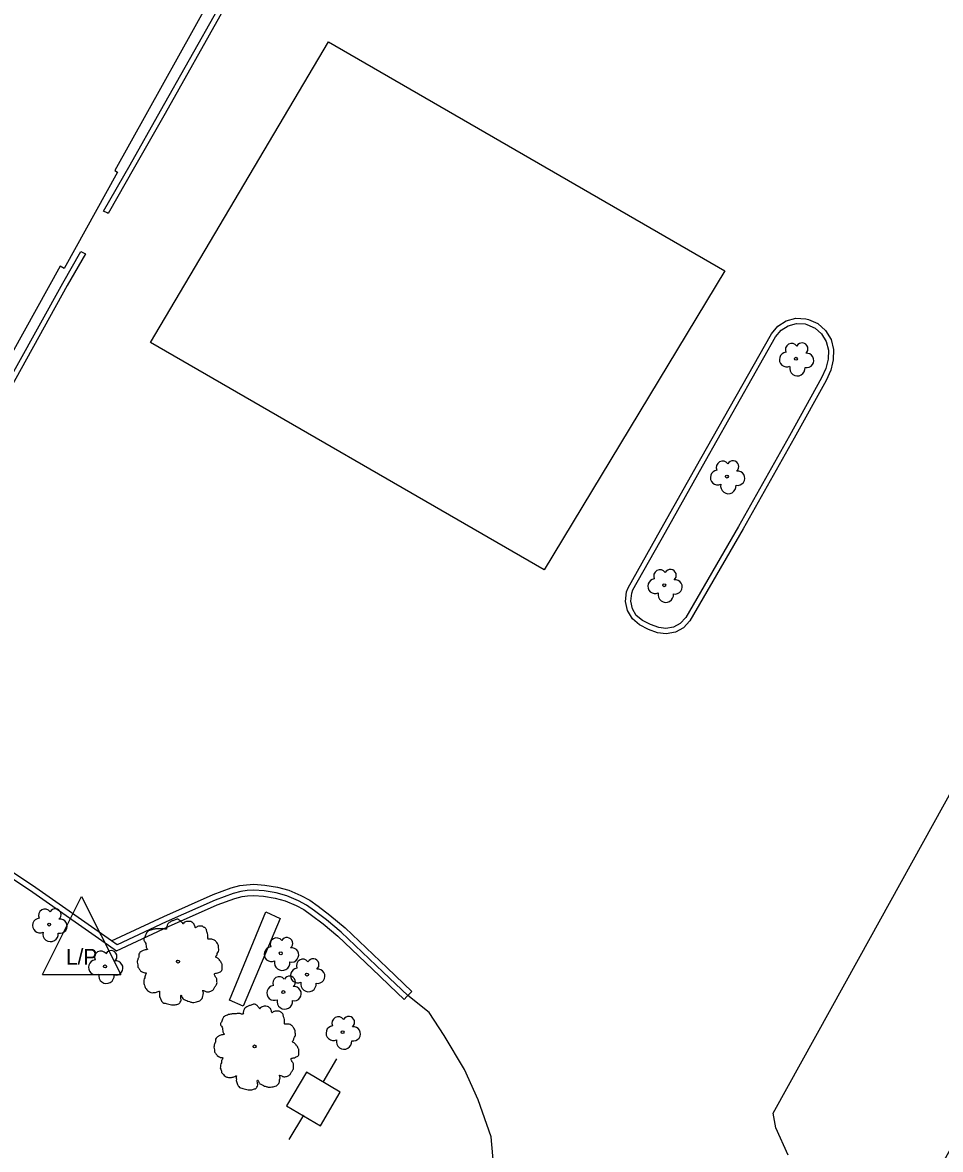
# Model space of a CAD drawing. Extents: x 2161152 to 2175754, y 602179 to 617749.
# Drawn here: x 2173654.5 to 2173771.8, y 616255.2 to 616399.3 of the extents above; entities that cross this region are included whole.
import ezdxf

# ---------------------------------------------------------------- set-up
doc = ezdxf.new("R2010")
doc.units = 0
for name, color, linetype in [('RD_EX_Bldg', 7, 'Continuous'), ('RD_EX_BldgApp', 7, 'Continuous'), ('RD_EX_BldgApp_Sign', 7, 'Continuous'), ('RD_EX_Conc_Curb', 7, 'Continuous'), ('RD_EX_Conc_Gutter', 7, 'Continuous'), ('RD_EX_Parking_Asphalt', 7, 'Continuous'), ('RD_EX_Road', 7, 'Continuous'), ('RD_EX_UT', 7, 'Continuous'), ('RD_EX_VEG', 7, 'Continuous')]:
    doc.layers.add(name, color=color, linetype=linetype)

msp = doc.modelspace()

# ---------------------------------------------------------------- linework, layer by layer
at = {"layer": 'RD_EX_Bldg'}
msp.add_lwpolyline([(2173647.25, 616346.36), (2173617.17, 616363.05), (2173634.68, 616394.61), (2173627.98, 616398.33), (2173643.55, 616426.38), (2173680.5, 616405.88), (2173666.33, 616380.34), (2173666.67, 616380.15), (2173659.83, 616367.83), (2173659.32, 616368.11), (2173647.25, 616346.36)], dxfattribs=at)
at = {"layer": 'RD_EX_BldgApp'}
msp.add_lwpolyline([(2173670.86, 616358.36), (2173693.61, 616396.79), (2173744.23, 616367.52), (2173721.15, 616329.29), (2173670.86, 616358.36)], dxfattribs=at)
at = {"layer": 'RD_EX_BldgApp_Sign'}
msp.add_lwpolyline([(2173680.95, 616274.3), (2173685.62, 616285.58), (2173687.42, 616284.75), (2173682.71, 616273.51), (2173680.95, 616274.3)], dxfattribs=at)
at = {"layer": 'RD_EX_Conc_Curb'}
for points in [[(2173680.13, 616400.76), (2173672.73, 616387.64), (2173668.84, 616380.76), (2173665.48, 616374.84), (2173665.33, 616374.92), (2173664.88, 616375.15), (2173668.26, 616381.09), (2173672.15, 616387.96), (2173679.54, 616401.08)], [(2173650.77, 616349.97), (2173659.66, 616365.96), (2173661.95, 616369.98), (2173662.41, 616369.78), (2173662.56, 616369.7), (2173660.24, 616365.63), (2173651.36, 616349.65)], [(2173739.79, 616322.79), (2173738.98, 616321.9), (2173737.93, 616321.32), (2173736.75, 616321.11), (2173735.64, 616321.26), (2173734.5, 616321.68), (2173733.34, 616322.26), (2173732.43, 616323.05), (2173731.81, 616324.09), (2173731.55, 616325.27), (2173731.69, 616326.48), (2173731.89, 616327.01), (2173736.09, 616334.44), (2173741.19, 616343.55), (2173750.19, 616359.46), (2173751.01, 616360.44), (2173752.09, 616361.13), (2173753.32, 616361.46), (2173754.6, 616361.4), (2173754.93, 616361.32), (2173756.14, 616360.77), (2173757.13, 616359.89), (2173757.82, 616358.76), (2173758.15, 616357.48), (2173758.1, 616356.15), (2173758, 616355.75), (2173757.8, 616354.82), (2173757.18, 616353.52), (2173753.1, 616346.11), (2173746.59, 616334.52), (2173739.79, 616322.79)], [(2173739.25, 616323.19), (2173738.56, 616322.43), (2173737.7, 616321.96), (2173736.73, 616321.78), (2173735.8, 616321.91), (2173734.76, 616322.3), (2173733.71, 616322.82), (2173732.94, 616323.48), (2173732.44, 616324.33), (2173732.23, 616325.31), (2173732.35, 616326.32), (2173732.5, 616326.73), (2173736.67, 616334.12), (2173741.77, 616343.23), (2173750.74, 616359.08), (2173751.45, 616359.94), (2173752.36, 616360.51), (2173753.39, 616360.79), (2173754.5, 616360.74), (2173754.71, 616360.68), (2173755.77, 616360.2), (2173756.61, 616359.46), (2173757.2, 616358.5), (2173757.49, 616357.4), (2173757.43, 616356.24), (2173757.35, 616355.9), (2173757.16, 616355.03), (2173756.58, 616353.83), (2173752.52, 616346.44), (2173746.01, 616334.85), (2173739.25, 616323.19)], [(2173644.6, 616295.56), (2173655.42, 616288.39), (2173665.5, 616281.31), (2173666.52, 616280.6), (2173666.52, 616280.6), (2173673.16, 616283.69), (2173679.4, 616286.47), (2173681.63, 616287.29), (2173682.56, 616287.55), (2173683.26, 616287.63), (2173684.09, 616287.69), (2173685.3, 616287.6), (2173686.78, 616287.35), (2173688.06, 616287.01), (2173689.48, 616286.38), (2173690.47, 616285.87), (2173691.44, 616285.16), (2173692.92, 616284.06), (2173694.81, 616282.47), (2173700.14, 616277.39), (2173701.42, 616276.17), (2173703.28, 616274.39), (2173703.62, 616274.75), (2173703.74, 616274.87), (2173700.6, 616277.87), (2173695.25, 616282.97), (2173693.34, 616284.58), (2173691.84, 616285.69), (2173690.82, 616286.44), (2173689.77, 616286.98), (2173688.28, 616287.64), (2173686.92, 616288), (2173685.38, 616288.26), (2173684.09, 616288.36), (2173683.2, 616288.29), (2173682.43, 616288.2), (2173681.42, 616287.93), (2173679.15, 616287.08), (2173672.88, 616284.29), (2173666.59, 616281.36), (2173665.88, 616281.86), (2173655.8, 616288.94), (2173644.97, 616296.12)]]:
    msp.add_lwpolyline(points, dxfattribs=at)
at = {"layer": 'RD_EX_Conc_Gutter'}
msp.add_lwpolyline([(2173665.88, 616281.86), (2173672.57, 616284.98), (2173678.87, 616287.78), (2173681.19, 616288.64), (2173682.29, 616288.94), (2173683.13, 616289.04), (2173684.09, 616289.11), (2173685.47, 616289.01), (2173687.08, 616288.74), (2173688.53, 616288.35), (2173690.09, 616287.65), (2173691.22, 616287.08), (2173692.28, 616286.3), (2173693.8, 616285.17), (2173695.75, 616283.52), (2173701.12, 616278.41), (2173704.26, 616275.42), (2173703.74, 616274.87)], dxfattribs=at)
at = {"layer": 'RD_EX_Parking_Asphalt'}
msp.add_lwpolyline([(2173708.93, 616234.18), (2173711.72, 616240.3), (2173714.02, 616245.32), (2173714.78, 616249.38), (2173714.74, 616252.94), (2173714.38, 616256.83), (2173712.72, 616261.55), (2173710.98, 616265.42), (2173708.39, 616269.77), (2173706.49, 616272.71), (2173703.74, 616274.87)], dxfattribs=at)
at = {"layer": 'RD_EX_Road'}
msp.add_lwpolyline([(2173752.35, 616254.46), (2173750.76, 616257.96), (2173750.44, 616259.84), (2173761.32, 616279.55), (2173773.65, 616301.79), (2173786.76, 616325.03), (2173798.04, 616345.07), (2173803.28, 616353.89), (2173804.13, 616354.96), (2173805.97, 616356.26), (2173816.33, 616360.71), (2173821.12, 616362.3), (2173823.63, 616362.63), (2173825.63, 616362.48), (2173827.55, 616361.41), (2173828.79, 616359.56), (2173829.27, 616357.97), (2173828.93, 616356.23), (2173818.27, 616336.22), (2173806.71, 616315.66), (2173796.58, 616298.07), (2173782.35, 616272.16), (2173777.23, 616262.74), (2173771.81, 616252.97)], dxfattribs=at)
at = {"layer": 'RD_EX_UT'}
for p, q in [((2173657.07, 616277.56), (2173662.07, 616287.56)), ((2173662.07, 616287.56), (2173667.07, 616277.56)), ((2173657.07, 616277.56), (2173667.07, 616277.56)), ((2173694.65, 616266.8), (2173692.89, 616263.81)), ((2173690.81, 616265.08), (2173688.26, 616260.78)), ((2173695.11, 616262.54), (2173690.81, 616265.08)), ((2173692.57, 616258.23), (2173695.11, 616262.54)), ((2173688.26, 616260.78), (2173692.57, 616258.23)), ((2173690.4, 616259.6), (2173688.55, 616256.47))]:
    msp.add_line(p, q, dxfattribs=at)
at = {"layer": 'RD_EX_VEG'}
for centre, radius in [((2173753.33, 616356.28), 0.188), ((2173744.51, 616341.22), 0.188), ((2173736.51, 616327.33), 0.188), ((2173657.92, 616283.96), 0.188), ((2173687.51, 616280.28), 0.188), ((2173665.06, 616278.6), 0.188), ((2173674.38, 616279.23), 0.188), ((2173674.37, 616279.22), 0.000075), ((2173690.86, 616277.56), 0.188), ((2173687.84, 616275.33), 0.188), ((2173695.41, 616270.2), 0.188), ((2173684.17, 616268.38), 0.188), ((2173684.16, 616268.37), 0.000075)]:
    msp.add_circle(centre, radius, dxfattribs=at)
for centre, radius, start, end in [((2173752.79, 616357.44), 0.813, 34.9763, 204.756), ((2173754.12, 616357.56), 0.746, 308.7626, 152.0467), ((2173752.16, 616356.17), 0.943, 96.4518, 294.734), ((2173754.71, 616356.07), 0.914, 256.5667, 98.1046), ((2173753.52, 616355.08), 0.988, 166.8827, 5.7589), ((2173745.29, 616342.5), 0.746, 308.7626, 152.0467), ((2173743.34, 616341.1), 0.943, 96.4518, 294.734), ((2173743.97, 616342.38), 0.813, 34.9763, 204.756), ((2173745.89, 616341.01), 0.914, 256.5667, 98.1046), ((2173744.7, 616340.02), 0.988, 166.8827, 5.7589), ((2173735.97, 616328.49), 0.813, 34.9763, 204.756), ((2173737.3, 616328.6), 0.746, 308.7626, 152.0467), ((2173735.34, 616327.21), 0.943, 96.4518, 294.734), ((2173737.89, 616327.12), 0.914, 256.5667, 98.1046), ((2173736.7, 616326.13), 0.988, 166.8827, 5.7589), ((2173657.38, 616285.12), 0.813, 34.9763, 204.756), ((2173658.7, 616285.23), 0.746, 308.7626, 152.0467), ((2173656.75, 616283.84), 0.943, 96.4518, 294.734), ((2173659.3, 616283.75), 0.914, 256.5667, 98.1046), ((2173658.1, 616282.76), 0.988, 166.8827, 5.7589), ((2173686.97, 616281.44), 0.813, 34.9763, 204.756), ((2173688.29, 616281.55), 0.746, 308.7626, 152.0467), ((2173664.52, 616279.77), 0.813, 34.9763, 204.756), ((2173665.84, 616279.88), 0.746, 308.7626, 152.0467), ((2173686.33, 616280.16), 0.943, 96.4518, 294.734), ((2173688.89, 616280.07), 0.914, 256.5667, 98.1046), ((2173663.89, 616278.49), 0.943, 96.4518, 294.734), ((2173666.44, 616278.4), 0.914, 256.5667, 98.1046), ((2173687.69, 616279.08), 0.988, 166.8827, 5.7589), ((2173690.32, 616278.72), 0.813, 34.9763, 204.756), ((2173691.65, 616278.83), 0.746, 308.7626, 152.0467), ((2173665.24, 616277.41), 0.988, 166.8827, 5.7589), ((2173687.3, 616276.49), 0.813, 34.9763, 204.756), ((2173688.63, 616276.61), 0.746, 308.7626, 152.0467), ((2173689.69, 616277.44), 0.943, 96.4518, 294.734), ((2173692.24, 616277.35), 0.914, 256.5667, 98.1046), ((2173686.67, 616275.21), 0.943, 96.4518, 294.734), ((2173689.22, 616275.12), 0.914, 256.5667, 98.1046), ((2173691.05, 616276.36), 0.988, 166.8827, 5.7589), ((2173688.03, 616274.13), 0.988, 166.8827, 5.7589), ((2173694.87, 616271.36), 0.813, 34.9763, 204.756), ((2173696.2, 616271.47), 0.746, 308.7626, 152.0467), ((2173694.24, 616270.08), 0.943, 96.4518, 294.734), ((2173696.79, 616269.99), 0.914, 256.5667, 98.1046), ((2173695.6, 616269), 0.988, 166.8827, 5.7589)]:
    msp.add_arc(centre, radius, start, end, dxfattribs=at)
for points in [[(2173674.48, 616284.61), (2173674.25, 616284.63), (2173674.01, 616284.55), (2173673.82, 616284.48), (2173673.65, 616284.42), (2173673.48, 616284.34), (2173673.26, 616284.21), (2173673.09, 616284.06), (2173673, 616283.88), (2173672.96, 616283.71), (2173672.92, 616283.5), (2173672.92, 616283.37), (2173672.83, 616283.35), (2173672.71, 616283.37), (2173672.53, 616283.43), (2173672.34, 616283.43), (2173672.15, 616283.43), (2173671.89, 616283.41), (2173671.63, 616283.41), (2173671.42, 616283.37), (2173671.18, 616283.33), (2173670.9, 616283.24), (2173670.63, 616283.14), (2173670.41, 616282.96), (2173670.22, 616282.6), (2173670.13, 616282.34), (2173670.02, 616282.15), (2173670.13, 616281.81), (2173670.26, 616281.55), (2173670.28, 616281.4), (2173670.33, 616281.08), (2173670.41, 616280.91), (2173670.5, 616280.76), (2173670.45, 616280.75), (2173670.17, 616280.71), (2173669.94, 616280.63), (2173669.62, 616280.46), (2173669.45, 616280.3), (2173669.38, 616280.05), (2173669.36, 616279.79), (2173669.28, 616279.64), (2173669.23, 616279.43), (2173669.21, 616279.38), (2173669.17, 616279.13), (2173669.25, 616278.8), (2173669.27, 616278.53), (2173669.36, 616278.37), (2173669.47, 616278.23), (2173669.6, 616278.05), (2173669.9, 616277.88), (2173670.15, 616277.8), (2173670.3, 616277.78), (2173670.17, 616277.41), (2173670.13, 616277.15), (2173670.03, 616276.85), (2173670.03, 616276.79), (2173670, 616276.44), (2173670.11, 616276.19), (2173670.17, 616275.91), (2173670.3, 616275.74), (2173670.5, 616275.52), (2173670.75, 616275.35), (2173671.12, 616275.25), (2173671.42, 616275.27), (2173671.85, 616275.4), (2173672.04, 616275.46), (2173672.02, 616275.33), (2173672.04, 616275.05), (2173672.04, 616274.73), (2173672.15, 616274.49), (2173672.23, 616274.28), (2173672.34, 616274.09), (2173672.58, 616273.92), (2173672.88, 616273.87), (2173673.2, 616273.76), (2173673.54, 616273.7), (2173673.91, 616273.68), (2173674.36, 616273.79), (2173674.57, 616273.89), (2173674.65, 616274.02), (2173674.8, 616274.3), (2173674.76, 616274.47), (2173674.78, 616274.92), (2173674.85, 616274.79), (2173674.98, 616274.52), (2173675.36, 616274.3), (2173675.66, 616274.17), (2173676.01, 616274.05), (2173676.24, 616274), (2173676.59, 616274.05), (2173676.88, 616274.11), (2173677.16, 616274.2), (2173677.38, 616274.41), (2173677.51, 616274.62), (2173677.55, 616274.82), (2173677.61, 616275.1), (2173677.64, 616275.24)], [(2173677.64, 616275.24), (2173677.59, 616275.37), (2173677.55, 616275.55), (2173677.61, 616275.54), (2173677.74, 616275.5), (2173677.94, 616275.4), (2173678.11, 616275.35), (2173678.36, 616275.37), (2173678.56, 616275.44), (2173678.9, 616275.65), (2173679.11, 616276), (2173679.31, 616276.3), (2173679.37, 616276.55), (2173679.33, 616276.72), (2173679.31, 616277.09), (2173679.16, 616277.28), (2173679.12, 616277.37), (2173679.05, 616277.67), (2173679.11, 616277.71), (2173679.31, 616277.75), (2173679.59, 616277.84), (2173679.8, 616277.93), (2173679.97, 616278.07), (2173680.02, 616278.23), (2173680.01, 616278.53), (2173680.04, 616278.83), (2173679.99, 616278.95), (2173679.91, 616279.06), (2173679.86, 616279.21), (2173679.74, 616279.32), (2173679.67, 616279.43), (2173679.59, 616279.51), (2173679.5, 616279.62), (2173679.37, 616279.72), (2173679.26, 616279.75), (2173679.22, 616279.86), (2173679.33, 616280.01), (2173679.37, 616280.09), (2173679.39, 616280.26), (2173679.56, 616280.52), (2173679.59, 616280.82), (2173679.56, 616281.14), (2173679.52, 616281.35), (2173679.41, 616281.55), (2173679.26, 616281.74), (2173679.16, 616281.87), (2173679.03, 616281.96), (2173678.79, 616282.06), (2173678.6, 616282.1), (2173678.34, 616282.1), (2173678.19, 616282.13), (2173678.21, 616282.17), (2173678.21, 616282.28), (2173678.21, 616282.49), (2173678.15, 616282.83), (2173678.04, 616283.2), (2173678.04, 616283.22), (2173677.96, 616283.41), (2173677.79, 616283.56), (2173677.66, 616283.63), (2173677.51, 616283.73), (2173677.33, 616283.74), (2173677.1, 616283.74), (2173676.89, 616283.71), (2173676.74, 616283.63), (2173676.61, 616283.54), (2173676.56, 616283.65), (2173676.48, 616283.88), (2173676.44, 616283.99), (2173676.33, 616284.12), (2173676.16, 616284.27), (2173675.83, 616284.36), (2173675.36, 616284.31), (2173675.13, 616284.16), (2173675.02, 616284.03), (2173674.98, 616284.12), (2173674.83, 616284.27), (2173674.76, 616284.4), (2173674.63, 616284.49), (2173674.51, 616284.57), (2173674.44, 616284.61)], [(2173684.27, 616273.75), (2173684.05, 616273.77), (2173683.8, 616273.7), (2173683.62, 616273.62), (2173683.45, 616273.57), (2173683.28, 616273.49), (2173683.05, 616273.36), (2173682.89, 616273.21), (2173682.79, 616273.02), (2173682.75, 616272.86), (2173682.72, 616272.65), (2173682.72, 616272.52), (2173682.62, 616272.5), (2173682.51, 616272.52), (2173682.32, 616272.57), (2173682.14, 616272.57), (2173681.95, 616272.57), (2173681.69, 616272.56), (2173681.42, 616272.56), (2173681.22, 616272.52), (2173680.97, 616272.48), (2173680.69, 616272.39), (2173680.43, 616272.29), (2173680.21, 616272.11), (2173680.02, 616271.75), (2173679.92, 616271.49), (2173679.81, 616271.3), (2173679.92, 616270.96), (2173680.06, 616270.7), (2173680.07, 616270.55), (2173680.13, 616270.23), (2173680.21, 616270.06), (2173680.3, 616269.91), (2173680.24, 616269.89), (2173679.96, 616269.86), (2173679.74, 616269.78), (2173679.42, 616269.61), (2173679.25, 616269.44), (2173679.17, 616269.2), (2173679.16, 616268.94), (2173679.08, 616268.79), (2173679.02, 616268.58), (2173679.01, 616268.53), (2173678.97, 616268.28), (2173679.04, 616267.94), (2173679.06, 616267.68), (2173679.16, 616267.51), (2173679.27, 616267.38), (2173679.4, 616267.2), (2173679.7, 616267.03), (2173679.94, 616266.95), (2173680.09, 616266.93), (2173679.96, 616266.56), (2173679.92, 616266.3), (2173679.83, 616266), (2173679.83, 616265.94), (2173679.79, 616265.58), (2173679.91, 616265.34), (2173679.96, 616265.06), (2173680.09, 616264.89), (2173680.3, 616264.67), (2173680.54, 616264.5), (2173680.92, 616264.4), (2173681.22, 616264.42), (2173681.65, 616264.55), (2173681.84, 616264.61), (2173681.82, 616264.48), (2173681.84, 616264.2), (2173681.84, 616263.88), (2173681.95, 616263.63), (2173682.02, 616263.43), (2173682.14, 616263.24), (2173682.38, 616263.07), (2173682.68, 616263.02), (2173683, 616262.9), (2173683.33, 616262.85), (2173683.71, 616262.83), (2173684.16, 616262.94), (2173684.37, 616263.03), (2173684.44, 616263.17), (2173684.59, 616263.45), (2173684.55, 616263.62), (2173684.57, 616264.07), (2173684.65, 616263.93), (2173684.78, 616263.67), (2173685.15, 616263.45), (2173685.45, 616263.32), (2173685.81, 616263.2), (2173686.03, 616263.15), (2173686.39, 616263.2), (2173686.67, 616263.26), (2173686.95, 616263.35), (2173687.18, 616263.56), (2173687.31, 616263.77), (2173687.35, 616263.97), (2173687.4, 616264.25), (2173687.44, 616264.38)], [(2173687.44, 616264.38), (2173687.38, 616264.52), (2173687.35, 616264.7), (2173687.4, 616264.68), (2173687.53, 616264.65), (2173687.74, 616264.55), (2173687.91, 616264.5), (2173688.15, 616264.52), (2173688.36, 616264.59), (2173688.7, 616264.8), (2173688.9, 616265.15), (2173689.11, 616265.45), (2173689.16, 616265.7), (2173689.13, 616265.86), (2173689.11, 616266.24), (2173688.96, 616266.43), (2173688.92, 616266.52), (2173688.85, 616266.82), (2173688.9, 616266.86), (2173689.11, 616266.9), (2173689.39, 616266.99), (2173689.59, 616267.08), (2173689.76, 616267.21), (2173689.82, 616267.38), (2173689.8, 616267.68), (2173689.84, 616267.98), (2173689.78, 616268.09), (2173689.71, 616268.21), (2173689.65, 616268.36), (2173689.54, 616268.47), (2173689.46, 616268.58), (2173689.39, 616268.66), (2173689.29, 616268.77), (2173689.16, 616268.86), (2173689.05, 616268.9), (2173689.01, 616269.01), (2173689.13, 616269.16), (2173689.16, 616269.24), (2173689.18, 616269.41), (2173689.35, 616269.67), (2173689.39, 616269.97), (2173689.35, 616270.29), (2173689.31, 616270.49), (2173689.2, 616270.7), (2173689.05, 616270.89), (2173688.96, 616271.02), (2173688.83, 616271.11), (2173688.58, 616271.21), (2173688.4, 616271.24), (2173688.13, 616271.24), (2173687.98, 616271.28), (2173688, 616271.32), (2173688, 616271.43), (2173688, 616271.64), (2173687.95, 616271.97), (2173687.83, 616272.35), (2173687.83, 616272.37), (2173687.76, 616272.56), (2173687.59, 616272.71), (2173687.46, 616272.78), (2173687.31, 616272.87), (2173687.12, 616272.89), (2173686.9, 616272.89), (2173686.69, 616272.86), (2173686.54, 616272.78), (2173686.41, 616272.69), (2173686.35, 616272.8), (2173686.28, 616273.02), (2173686.24, 616273.14), (2173686.13, 616273.27), (2173685.96, 616273.42), (2173685.62, 616273.51), (2173685.15, 616273.46), (2173684.93, 616273.31), (2173684.82, 616273.17), (2173684.78, 616273.27), (2173684.63, 616273.42), (2173684.55, 616273.55), (2173684.42, 616273.64), (2173684.31, 616273.72), (2173684.23, 616273.75)]]:
    msp.add_spline(points, degree=3, dxfattribs=at)

# ---------------------------------------------------------------- texts
at = {"layer": 'RD_EX_UT'}
msp.add_text('L/P', height=2, dxfattribs=at).set_placement((2173660.06, 616278.84))

doc.saveas('drawing.dxf')
